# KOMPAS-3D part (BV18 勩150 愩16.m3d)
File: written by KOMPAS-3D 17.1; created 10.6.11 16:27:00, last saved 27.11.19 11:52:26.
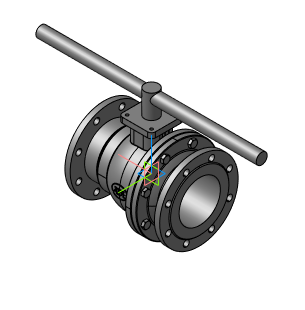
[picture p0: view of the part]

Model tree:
1. Плоскость XY
2. Плоскость ZX
3. Плоскость ZY
4. Ось X
5. Ось Y
6. Ось Z
7. Начало координат
8. Операция без истории:4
